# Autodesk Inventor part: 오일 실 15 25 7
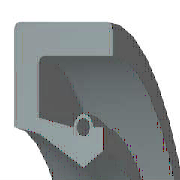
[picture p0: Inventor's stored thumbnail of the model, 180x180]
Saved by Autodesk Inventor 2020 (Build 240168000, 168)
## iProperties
Created: 2012-02
Part Number: 오일 실 15 25 7
Material: 고무
Description: 오일 실 - 스프링 장착, 금속 케이스 SM
Document SubType Name: Modeling
Standard: JIS B 2402
Designer: mdu-01
Standards Organization: JIS
Language: ko-KR
Size Designation: 15 25 7 A
Categories: <MemberInstance><Categories><Category DisplayName="샤프트 부품" InternalName="7f7aeb1f-a693-4053-b835-cee3144e0d98" Mnemonic="SHFT"><Category DisplayName="실링" Intern
Density: 0.93 g/cm^3
Appearance: Rubber-Black
IsCustomPart: 1
Author: mdu-01
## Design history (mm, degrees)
body "Solid1"
revolve "회전1" stored, may be unused: angle "d33" = 360 deg
fillet "모깎기1" dims "d34" = 0.35 (= 0.05 x b)
chamfer "모따기1" distance "d35" = 0.7 (= 0.1 x b); stored, may be unused: second distance "d36" = 0.35 (= 0.05 x b), angle "d41" = 45 deg
sketch "스케치2"
  geometry: L1 (8.714, -5.158)-(9.184, -7); L2 (8.214, -4.55)-(8.714, -5.158); L3 (7.5, -1.75)-(8.214, -4.55); L4 (8.167, -0.875)-(7.5, -1.75); L5 (9.284, -0.875)-(8.167, -0.875); L6 (9.284, -1.575)-(9.284, -0.875); L7 (9.284, -5.25)-(9.284, -2.975); L8 (10.5, -5.25)-(9.284, -5.25); L9 (11.5, -1.75)-(10.5, -5.25); L10 (11.5, 0)-(11.5, -1.75); L11 (12.5, 0)-(11.5, 0); L12 (12.5, -7)-(12.5, 0); L13 (9.184, -7)-(12.5, -7); L14 (0, -9.6)-(0, 1.6) reference; L15 (28, 0)-(14, 0) reference; A1 r 0.7 centre (9.284, -2.275) between (9.284, -2.975) and (9.284, -1.575)
  constraints: 26 end point, 4 horizontal, 4 vertical, 2 point on circle, 1 centre point, 1 collinear, 1 parallel
  dimensions: "d2" = 7 distance of L12.start L11.start (= b); "d4" = 0.875 vertical distance of L10.start L5.start (= 0.125 x b); "d6" = 1 distance of L11.start L10.start (= 0.1 x dd - 0.1 x Diam); "d8" = 1.75 distance of L10.start L9.start (= 0.25 x b); "d10" = 1.75 vertical distance of L8.start L1.end (= 0.25 x b); "d12" = 1 horizontal distance of L9.start L8.start (= 0.1 x dd - 0.1 x Diam); "d14" = 0.7 radius of A1 (= 0.1 x b); "d16" = 0 horizontal distance of A1.centre L7.end; "d18" = 0.7 distance of L6.start L5.start (= 0.1 x b); "d20" = 0.66667 horizontal distance of L4.start L3.start (= 0.0666667 x dd - 0.0666667 x Diam); "d22" = 0.1 horizontal distance of L7.start L1.end (= 0.01 x dd - 0.01 x Diam); "d24" = 0.875 vertical distance of L4.start L3.start (= 0.125 x b); "d26" = 2.8 vertical distance of L3.start L2.start (= 0.4 x b); "d28" = 0.71429 horizontal distance of L3.start L2.start (= 0.0714286 x dd - 0.0714286 x Diam); "d30" = 1.84211 vertical distance of L1.start L1.end (= 0.263158 x b); "d32" = 0.5 horizontal distance of L2.start L1.start (= 0.05 x dd - 0.05 x Diam); "d37" = 0 distance between parallel lines of L15 L11; "d38" = 12.5 distance between parallel lines of L14 L12 (= 0.5 x dd); "d39" = 7.5 distance from line of L14 L3.start (= 0.5 x Diam)
other parameters: "dd" = 25 [user parameter; used in 7 equation terms], "Diam" = 15 [user parameter; used in 7 equation terms], "b" = 7 [user parameter; used in 12 equation terms], "d1" = 8 (derived), "d3" = 1 (derived), "d5" = 2 (derived), "d7" = 2 (derived), "d9" = 2 (derived), "d11" = 2 (derived), "d13" = 0.8 (derived), "d15" = 0 (derived), "d17" = 0.8 (derived), "d19" = 1.33333 (derived), "d21" = 0.2 (derived), "d23" = 1 (derived), "d25" = 3.2 (derived), "d27" = 1.42857 (derived), "d29" = 2.10526 (derived), "d31" = 1 (derived), "d40" = 0
